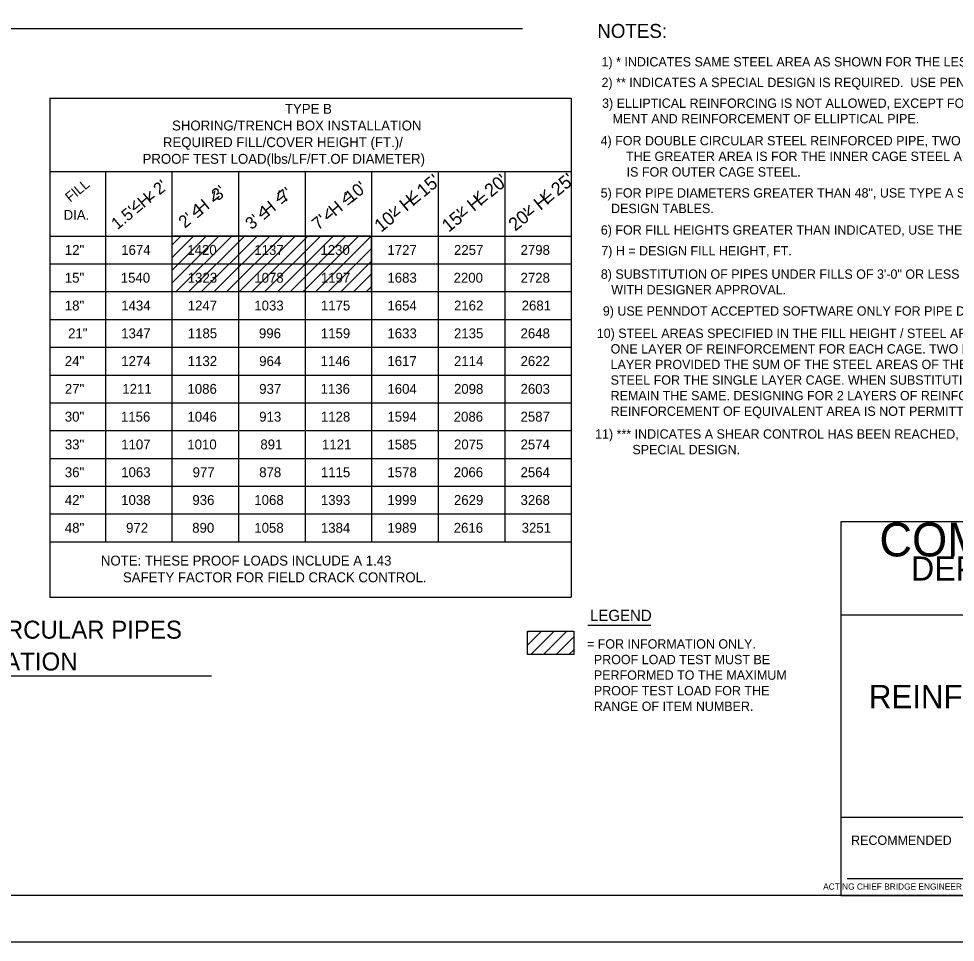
# Model space of a CAD drawing. Extents: x -22562 to -18409, y 3991 to 7171.
# Drawn here: x -20023 to -19722.1, y 3991.4 to 4287.9 of the extents above; entities that cross this region are included whole.
import ezdxf

# ---------------------------------------------------------------- set-up
doc = ezdxf.new("R2010")
doc.units = 0
for name, color, linetype in [('1', 7, 'Continuous'), ('2', 7, 'Continuous'), ('3', 7, 'Continuous'), ('4', 7, 'Continuous'), ('PLT-BNDY', 7, 'Continuous')]:
    doc.layers.add(name, color=color, linetype=linetype)

msp = doc.modelspace()

# ---------------------------------------------------------------- linework, layer by layer
at = {"layer": '1'}
for p, q in [((-20012.97, 4238.78), (-20012.97, 4238.78)), ((-19854.27, 4229.74), (-19853.91, 4233)), ((-19981.02, 4229.57), (-19980.69, 4232.54)), ((-19981.02, 4229.57), (-19979.37, 4230.92)), ((-19960.54, 4229.27), (-19959.91, 4232.58)), ((-19960.54, 4229.27), (-19958.55, 4230.91)), ((-19939.82, 4229.44), (-19939.2, 4232.71)), ((-19918.56, 4229.01), (-19918.03, 4232.23)), ((-19897.1, 4229.47), (-19896.73, 4232.73)), ((-19875.68, 4229.29), (-19875.32, 4232.56)), ((-19986.06, 4226.54), (-19985.73, 4229.51)), ((-19966.74, 4224.97), (-19966.12, 4228.29)), ((-19945.35, 4224.43), (-19944.73, 4227.71)), ((-19924.15, 4223.72), (-19923.62, 4226.94)), ((-19902.28, 4224.43), (-19901.92, 4227.7)), ((-19880.82, 4224.36), (-19880.46, 4227.62)), ((-19859.31, 4224.71), (-19858.95, 4227.97)), ((-19924.05, 4223.75), (-19922.16, 4225.3)), ((-19902.21, 4224.35), (-19900.41, 4225.83)), ((-19880.61, 4224.41), (-19878.81, 4225.89)), ((-19859.15, 4224.76), (-19857.35, 4226.24)), ((-20012.97, 4218.09), (-20012.97, 4218.09)), ((-19973.75, 4218.09), (-19973.75, 4218.09)), ((-19973.75, 4215.2), (-19970.86, 4218.09)), ((-19973.75, 4211.12), (-19966.79, 4218.09)), ((-19973.75, 4207.05), (-19962.71, 4218.09)), ((-19973.75, 4202.97), (-19958.63, 4218.09)), ((-19972.39, 4200.25), (-19954.55, 4218.09)), ((-19968.32, 4200.25), (-19950.47, 4218.09)), ((-19964.24, 4200.25), (-19946.4, 4218.09)), ((-19960.16, 4200.25), (-19942.32, 4218.09)), ((-19956.08, 4200.25), (-19938.24, 4218.09)), ((-19952, 4200.25), (-19934.16, 4218.09)), ((-19947.93, 4200.25), (-19930.09, 4218.09)), ((-19943.85, 4200.25), (-19926.01, 4218.09)), ((-19939.77, 4200.25), (-19921.93, 4218.09)), ((-19935.69, 4200.25), (-19917.85, 4218.09)), ((-19931.62, 4200.25), (-19913.78, 4218.09)), ((-19927.54, 4200.25), (-19909.7, 4218.09)), ((-19909.6, 4218.09), (-19909.6, 4218.09)), ((-20004.05, 4213.63), (-20004.05, 4213.63)), ((-19984.44, 4213.63), (-19984.44, 4213.63)), ((-19963.06, 4213.63), (-19963.06, 4213.63)), ((-19923.46, 4200.25), (-19909.6, 4214.1)), ((-19920.29, 4213.63), (-19920.29, 4213.63)), ((-19898.91, 4213.63), (-19898.91, 4213.63)), ((-19877.53, 4213.63), (-19877.53, 4213.63)), ((-19856.15, 4213.63), (-19856.15, 4213.63)), ((-20012.97, 4209.17), (-20012.97, 4209.17)), ((-19919.38, 4200.25), (-19909.6, 4210.02)), ((-19915.3, 4200.25), (-19909.6, 4205.95)), ((-20004.05, 4204.71), (-20004.05, 4204.71)), ((-19984.44, 4204.71), (-19984.44, 4204.71)), ((-19963.06, 4204.71), (-19963.06, 4204.71)), ((-19920.29, 4204.71), (-19920.29, 4204.71)), ((-19898.91, 4204.71), (-19898.91, 4204.71)), ((-19877.53, 4204.71), (-19877.53, 4204.71)), ((-19856.15, 4204.71), (-19856.15, 4204.71)), ((-20012.97, 4200.25), (-20012.97, 4200.25)), ((-19973.75, 4200.25), (-19973.75, 4200.25)), ((-19911.23, 4200.25), (-19909.6, 4201.87)), ((-19909.6, 4200.25), (-19909.6, 4200.25)), ((-20004.05, 4195.79), (-20004.05, 4195.79)), ((-19984.44, 4195.79), (-19984.44, 4195.79)), ((-19963.06, 4195.79), (-19963.06, 4195.79)), ((-19920.29, 4195.79), (-19920.29, 4195.79)), ((-19898.91, 4195.79), (-19898.91, 4195.79)), ((-19877.53, 4195.79), (-19877.53, 4195.79)), ((-19856.15, 4195.79), (-19856.15, 4195.79)), ((-20012.97, 4191.32), (-20012.97, 4191.32)), ((-20004.05, 4186.87), (-20004.05, 4186.87)), ((-19984.44, 4186.87), (-19984.44, 4186.87)), ((-19963.06, 4186.87), (-19963.06, 4186.87)), ((-19920.29, 4186.87), (-19920.29, 4186.87)), ((-19898.91, 4186.87), (-19898.91, 4186.87)), ((-19877.53, 4186.87), (-19877.53, 4186.87)), ((-19856.15, 4186.87), (-19856.15, 4186.87)), ((-20012.97, 4182.4), (-20012.97, 4182.4)), ((-20004.05, 4177.94), (-20004.05, 4177.94)), ((-19984.44, 4177.94), (-19984.44, 4177.94)), ((-19963.06, 4177.94), (-19963.06, 4177.94)), ((-19920.29, 4177.94), (-19920.29, 4177.94)), ((-19898.91, 4177.94), (-19898.91, 4177.94)), ((-19877.53, 4177.94), (-19877.53, 4177.94)), ((-19856.15, 4177.94), (-19856.15, 4177.94)), ((-20012.97, 4173.48), (-20012.97, 4173.48)), ((-20004.05, 4169.02), (-20004.05, 4169.02)), ((-19984.44, 4169.02), (-19984.44, 4169.02)), ((-19963.06, 4169.02), (-19963.06, 4169.02)), ((-19920.29, 4169.02), (-19920.29, 4169.02)), ((-19898.91, 4169.02), (-19898.91, 4169.02)), ((-19877.53, 4169.02), (-19877.53, 4169.02)), ((-19856.15, 4169.02), (-19856.15, 4169.02)), ((-20012.97, 4164.56), (-20012.97, 4164.56)), ((-20004.05, 4160.1), (-20004.05, 4160.1)), ((-19984.44, 4160.1), (-19984.44, 4160.1)), ((-19963.06, 4160.1), (-19963.06, 4160.1)), ((-19920.29, 4160.1), (-19920.29, 4160.1)), ((-19898.91, 4160.1), (-19898.91, 4160.1)), ((-19877.53, 4160.1), (-19877.53, 4160.1)), ((-19856.15, 4160.1), (-19856.15, 4160.1)), ((-20012.97, 4155.64), (-20012.97, 4155.64)), ((-20004.05, 4151.18), (-20004.05, 4151.18)), ((-19984.44, 4151.18), (-19984.44, 4151.18)), ((-19963.06, 4151.18), (-19963.06, 4151.18)), ((-19920.29, 4151.18), (-19920.29, 4151.18)), ((-19898.91, 4151.18), (-19898.91, 4151.18)), ((-19877.53, 4151.18), (-19877.53, 4151.18)), ((-19856.15, 4151.18), (-19856.15, 4151.18)), ((-20012.97, 4146.72), (-20012.97, 4146.72)), ((-20004.05, 4142.26), (-20004.05, 4142.26)), ((-19984.44, 4142.26), (-19984.44, 4142.26)), ((-19963.06, 4142.26), (-19963.06, 4142.26)), ((-19920.29, 4142.26), (-19920.29, 4142.26)), ((-19898.91, 4142.26), (-19898.91, 4142.26)), ((-19877.53, 4142.26), (-19877.53, 4142.26)), ((-19856.15, 4142.26), (-19856.15, 4142.26)), ((-20012.97, 4137.8), (-20012.97, 4137.8)), ((-20004.05, 4133.34), (-20004.05, 4133.34)), ((-19984.44, 4133.34), (-19984.44, 4133.34)), ((-19963.06, 4133.34), (-19963.06, 4133.34)), ((-19920.29, 4133.34), (-19920.29, 4133.34)), ((-19898.91, 4133.34), (-19898.91, 4133.34)), ((-19877.53, 4133.34), (-19877.53, 4133.34)), ((-19856.15, 4133.34), (-19856.15, 4133.34)), ((-20012.97, 4128.88), (-20012.97, 4128.88)), ((-20004.05, 4124.42), (-20004.05, 4124.42)), ((-19984.44, 4124.42), (-19984.44, 4124.42)), ((-19963.06, 4124.42), (-19963.06, 4124.42)), ((-19920.29, 4124.42), (-19920.29, 4124.42)), ((-19898.91, 4124.42), (-19898.91, 4124.42)), ((-19877.53, 4124.42), (-19877.53, 4124.42)), ((-19856.15, 4124.42), (-19856.15, 4124.42)), ((-19859.55, 4090.82), (-19859.16, 4091.21)), ((-19859.55, 4086.74), (-19855.08, 4091.21)), ((-19858.44, 4083.77), (-19851.01, 4091.21)), ((-19854.37, 4083.77), (-19846.93, 4091.21)), ((-19850.29, 4083.77), (-19844.68, 4089.37)), ((-19846.21, 4083.77), (-19844.68, 4085.3))]:
    msp.add_line(p, q, dxfattribs=at)
for points in [[(-19973.75, 4218.09), (-19973.75, 4200.25), (-19909.6, 4200.25), (-19909.6, 4218.09), (-19973.75, 4218.09)], [(-19859.55, 4091.21), (-19844.68, 4091.21), (-19844.68, 4083.77), (-19859.55, 4083.77), (-19859.55, 4091.21)]]:
    msp.add_lwpolyline(points, dxfattribs=at)
at = {"layer": '2'}
for p, q in [((-20088.88, 4284.71), (-19861.09, 4284.71)), ((-20012.97, 4262.32), (-19845.46, 4262.32)), ((-20012.97, 4262.32), (-20012.97, 4102.12)), ((-19845.46, 4262.32), (-19845.46, 4102.12)), ((-20012.97, 4238.78), (-19845.46, 4238.78)), ((-19995.13, 4238.78), (-19995.13, 4119.96)), ((-19973.75, 4238.78), (-19973.75, 4119.96)), ((-19952.36, 4238.78), (-19952.36, 4119.96)), ((-19930.98, 4238.78), (-19930.98, 4119.96)), ((-19909.6, 4238.78), (-19909.6, 4119.96)), ((-19888.22, 4238.78), (-19888.22, 4119.96)), ((-19866.84, 4238.78), (-19866.84, 4119.96)), ((-20012.97, 4218.09), (-19845.46, 4218.09)), ((-20012.97, 4209.17), (-19845.46, 4209.17)), ((-20012.97, 4200.25), (-19845.46, 4200.25)), ((-20012.97, 4191.32), (-19845.46, 4191.32)), ((-20012.97, 4182.4), (-19845.46, 4182.4)), ((-20012.97, 4173.48), (-19845.46, 4173.48)), ((-20012.97, 4164.56), (-19845.46, 4164.56)), ((-20012.97, 4155.64), (-19845.46, 4155.64)), ((-20012.97, 4146.72), (-19845.46, 4146.72)), ((-20012.97, 4137.8), (-19845.46, 4137.8)), ((-20012.97, 4128.88), (-19845.46, 4128.88)), ((-19558.85, 4126.37), (-19758.85, 4126.37)), ((-19758.85, 4126.37), (-19758.85, 4006.37)), ((-20012.97, 4119.96), (-19845.46, 4119.96)), ((-20012.97, 4102.12), (-19845.46, 4102.12)), ((-19558.85, 4096.37), (-19758.85, 4096.37)), ((-19840.17, 4093.2), (-19819.91, 4093.2)), ((-20181.42, 4076.88), (-19960.99, 4076.88)), ((-19558.85, 4031.37), (-19758.85, 4031.37)), ((-19756.85, 4011.87), (-19689.62, 4011.87)), ((-19558.85, 4006.37), (-20344.85, 4006.37)), ((-19758.85, 4006.37), (-19558.85, 4006.37))]:
    msp.add_line(p, q, dxfattribs=at)
at = {"layer": 'PLT-BNDY'}
msp.add_lwpolyline([(-20384.85, 4585.37), (-19543.85, 4585.37), (-19543.85, 3991.37), (-20384.85, 3991.37)], close=True, dxfattribs=at)

# ---------------------------------------------------------------- texts
at = {"layer": '1'}
for s, height, p in [('TYPE B', 3.172, (-19937.45, 4257.35)), ('SHORING/TRENCH BOX INSTALLATION', 3.1717, (-19973.7, 4251.99)), ('REQUIRED FILL/COVER HEIGHT (FT.)/', 3.1717, (-19976.64, 4246.64)), ('PROOF TEST LOAD(lbs/LF/FT.OF DIAMETER)', 3.1717, (-19983.17, 4241.29)), ('5) FOR PIPE DIAMETERS GREATER THAN 48", USE TYPE A SHORING/TRENCH BOX', 3, (-19836.03, 4230.45)), ('   DESIGN TABLES.', 3, (-19836.03, 4225.45)), ('DIA.', 3.172, (-20008.54, 4223.3)), ('6) FOR FILL HEIGHTS GREATER THAN INDICATED, USE THE PENNDOT ACCEPTED SOFTWARE.', 3, (-19835.97, 4218.55)), ('12"', 3.172, (-20008.15, 4212.04)), ('1674', 3.172, (-19990.04, 4212.04)), ('1420', 3.172, (-19968.8, 4212.04)), ('1230', 3.172, (-19926.04, 4212.04)), ('1727', 3.172, (-19904.52, 4212.04)), ('2257', 3.172, (-19883.14, 4212.04)), ('2798', 3.172, (-19861.76, 4212.04)), ('15"', 3.172, (-20008.15, 4203.12)), ('1540', 3.172, (-19990.18, 4203.12)), ('1323', 3.172, (-19968.66, 4203.12)), ('1197', 3.172, (-19925.9, 4203.12)), ('1683', 3.172, (-19904.52, 4203.12)), ('2200', 3.172, (-19883.27, 4203.12)), ('2728', 3.172, (-19861.76, 4203.12)), ('18"', 3.172, (-20008.15, 4194.2)), ('1434', 3.172, (-19990.04, 4194.2)), ('1247', 3.172, (-19968.66, 4194.2)), ('1175', 3.172, (-19925.9, 4194.2)), ('1654', 3.172, (-19904.52, 4194.2)), ('2162', 3.172, (-19883.14, 4194.2)), ('2681', 3.172, (-19861.4, 4194.2)), ('9) USE PENNDOT ACCEPTED SOFTWARE ONLY FOR PIPE DESIGNS NOT PROVIDED BY BD-636M.', 3, (-19835.33, 4192.54)), ('21"', 3.172, (-20007.1, 4185.28)), ('1347', 3.172, (-19990.04, 4185.28)), ('1185', 3.172, (-19968.66, 4185.28)), ('1159', 3.172, (-19925.91, 4185.28)), ('1633', 3.172, (-19904.52, 4185.28)), ('2135', 3.172, (-19883.14, 4185.28)), ('2648', 3.172, (-19861.76, 4185.28)), ('10) STEEL AREAS SPECIFIED IN THE FILL HEIGHT / STEEL AREA TABLES ARE TO BE ACHIEVED USING', 3, (-19837.28, 4185.38)), ('    ONE LAYER OF REINFORCEMENT FOR EACH CAGE. TWO LAYERS MAY BE SUBSTITUTED FOR ONE', 3, (-19837.28, 4180.38)), ('24"', 3.172, (-20008.15, 4176.36)), ('1274', 3.172, (-19990.04, 4176.36)), ('1132', 3.172, (-19968.66, 4176.36)), ('1146', 3.172, (-19925.99, 4176.36)), ('1617', 3.172, (-19904.52, 4176.36)), ('2114', 3.172, (-19883.14, 4176.36)), ('2622', 3.172, (-19861.76, 4176.36)), ('    LAYER PROVIDED THE SUM OF THE STEEL AREAS OF THE 2 LAYERS IS EQUAL TO THE AREA OF', 3, (-19837.28, 4175.37)), ('    STEEL FOR THE SINGLE LAYER CAGE. WHEN SUBSTITUTING, SPACING OF REINFORCEMENT IS TO', 3, (-19837.28, 4170.37)), ('27"', 3.172, (-20008.15, 4167.44)), ('1211', 3.172, (-19989.68, 4167.44)), ('1086', 3.172, (-19968.75, 4167.44)), ('1136', 3.172, (-19925.99, 4167.44)), ('1604', 3.172, (-19904.52, 4167.44)), ('2098', 3.172, (-19883.14, 4167.44)), ('2603', 3.172, (-19861.76, 4167.44)), ('    REMAIN THE SAME. DESIGNING FOR 2 LAYERS OF REINFORCEMENT AND PROVIDING ONE LAYER OF', 3, (-19837.28, 4165.36)), ('30"', 3.172, (-20008.15, 4158.52)), ('1156', 3.172, (-19990.13, 4158.52)), ('1046', 3.172, (-19968.75, 4158.52)), ('1128', 3.172, (-19925.9, 4158.52)), ('1594', 3.172, (-19904.52, 4158.52)), ('2086', 3.172, (-19883.23, 4158.52)), ('2587', 3.172, (-19861.76, 4158.52)), ('    REINFORCEMENT OF EQUIVALENT AREA IS NOT PERMITTED.', 3, (-19837.28, 4160.36)), ('11) *** INDICATES A SHEAR CONTROL HAS BEEN REACHED, USE PENNDOT ACCEPTED SOFTWARE FOR', 3, (-19837.82, 4153.05)), ('33"', 3.172, (-20008.15, 4149.6)), ('1107', 3.172, (-19990.04, 4149.6)), ('1010', 3.172, (-19968.8, 4149.6)), ('1121', 3.172, (-19925.54, 4149.6)), ('1585', 3.172, (-19904.52, 4149.6)), ('2075', 3.172, (-19883.14, 4149.6)), ('2574', 3.172, (-19861.76, 4149.6)), ('SPECIAL DESIGN.', 3, (-19825.82, 4148.04)), ('36"', 3.172, (-20008.15, 4140.68)), ('1063', 3.172, (-19990.04, 4140.68)), ('977', 3.172, (-19967.09, 4140.68)), ('1115', 3.172, (-19925.9, 4140.68)), ('1578', 3.172, (-19904.52, 4140.68)), ('2066', 3.172, (-19883.22, 4140.68)), ('2564', 3.172, (-19861.76, 4140.68)), ('42"', 3.172, (-20008.15, 4131.76)), ('1038', 3.172, (-19990.05, 4131.76)), ('936', 3.172, (-19967.17, 4131.76)), ('1393', 3.172, (-19925.9, 4131.76)), ('1999', 3.172, (-19904.53, 4131.76)), ('2629', 3.172, (-19883.15, 4131.76)), ('3268', 3.172, (-19861.76, 4131.76)), ('48"', 3.172, (-20008.15, 4122.84)), ('972', 3.172, (-19988.47, 4122.84)), ('890', 3.172, (-19967.23, 4122.84)), ('1384', 3.172, (-19925.9, 4122.84)), ('1989', 3.172, (-19904.53, 4122.84)), ('2616', 3.172, (-19883.23, 4122.84)), ('3251', 3.172, (-19861.4, 4122.84)), ('NOTE: THESE PROOF LOADS INCLUDE A 1.43', 3.1718, (-19996.56, 4112.31)), ('      SAFETY FACTOR FOR FIELD CRACK CONTROL.', 3.1718, (-19996.56, 4106.95)), ('= FOR INFORMATION ONLY.', 3, (-19840.44, 4085.65)), ('  PROOF LOAD TEST MUST BE', 3, (-19840.44, 4080.64)), ('  PERFORMED TO THE MAXIMUM', 3, (-19840.44, 4075.64)), ('  PROOF TEST LOAD FOR THE', 3, (-19840.44, 4070.63)), ('  RANGE OF ITEM NUMBER.', 3, (-19840.44, 4065.63))]:
    msp.add_text(s, height=height, dxfattribs=at).set_placement(p)
for s, height, p in [('FILL', 3.172, (-20006.43, 4228.81)), ('=', 3.93, (-19938.11, 4227.39)), ('=', 3.97, (-19916.75, 4226.98)), ('=', 4.22, (-19895.28, 4227.19)), ('=', 4.22, (-19873.78, 4227.21)), ('=', 4.22, (-19852.41, 4227.56)), ('=', 3.84, (-19984.44, 4224.52)), ('=', 3.97, (-19965.07, 4222.88)), ('=', 3.93, (-19943.69, 4222.36))]:
    msp.add_text(s, height=height, rotation=39.5, dxfattribs=at).set_placement(p)
at = {"layer": '2'}
for s, height, p in [('NOTES:', 4.5, (-19837.1, 4281.69)), ('COMMONWEALTH OF PENNSYLVANIA', 10.8525, (-19746.47, 4115.24)), ('DEPARTMENT OF TRANSPORTATION', 7.7332, (-19736.35, 4107.49)), ('DESIGN TABLES AND PROOF TEST LOAD TABLE FOR CIRCULAR PIPES', 5.7669, (-20236.21, 4088.84)), ('-TYPE B SHORING/TRENCH BOX INSTALLATION', 5.7669, (-20181.88, 4078.62)), ('REINFORCED CONCRETE PIPES', 7.5, (-19749.85, 4066.49)), ('       ACTING CHIEF BRIDGE ENGINEER', 2.0002, (-19769.76, 4008.24))]:
    msp.add_text(s, height=height, dxfattribs=at).set_placement(p)
msp.add_text('RECOMMENDED', height=3, rotation=360, dxfattribs=at).set_placement((-19755.58, 4022.62))
at = {"layer": '3'}
for s, height, p in [('1137', 3.172, (-19947.28, 4212.04)), ('1078', 3.172, (-19947.28, 4203.12)), ('8) SUBSTITUTION OF PIPES UNDER FILLS OF 3\'-0" OR LESS IS PERMITTED ONLY', 3, (-19835.97, 4204.37)), ('   WITH DESIGNER APPROVAL.', 3, (-19835.97, 4199.37)), ('1033', 3.172, (-19947.28, 4194.2)), ('996', 3.172, (-19945.79, 4185.28)), ('964', 3.172, (-19945.71, 4176.36)), ('937', 3.172, (-19945.71, 4167.44)), ('913', 3.172, (-19945.71, 4158.52)), ('891', 3.172, (-19945.34, 4149.6)), ('878', 3.172, (-19945.71, 4140.68)), ('1068', 3.172, (-19947.28, 4131.76)), ('1058', 3.172, (-19947.28, 4122.84))]:
    msp.add_text(s, height=height, dxfattribs=at).set_placement(p)
at = {"layer": '4'}
for s, height, p in [('1) * INDICATES SAME STEEL AREA AS SHOWN FOR THE LESSER CONCRETE STRENGTH.', 3, (-19835.75, 4272.53)), ('2) ** INDICATES A SPECIAL DESIGN IS REQUIRED.  USE PENNDOT ACCEPTED SOFTWARE.', 3, (-19835.75, 4265.9)), ('3) ELLIPTICAL REINFORCING IS NOT ALLOWED, EXCEPT FOR QUADRANT REINFORCE-', 3, (-19835.57, 4259.25)), ('   MENT AND REINFORCEMENT OF ELLIPTICAL PIPE.', 3, (-19835.57, 4254.25)), ('4) FOR DOUBLE CIRCULAR STEEL REINFORCED PIPE, TWO AREAS ARE SHOWN.', 3, (-19836.05, 4247.2)), ('THE GREATER AREA IS FOR THE INNER CAGE STEEL AND LESSER AREA', 3, (-19827.86, 4242.2)), ('IS FOR OUTER CAGE STEEL.', 3, (-19827.68, 4237.19)), ('7) H = DESIGN FILL HEIGHT, FT.', 3, (-19835.83, 4211.85)), ('LEGEND', 3.606, (-19839.46, 4094.5))]:
    msp.add_text(s, height=height, dxfattribs=at).set_placement(p)
for s, height, p in [("1.5'  H  2'", 3.8379, (-19991.28, 4219.93)), ("10'  H  15'", 4.2216, (-19906.55, 4219.1)), ("15'  H  20'", 4.2216, (-19884.86, 4219.11)), ("20'  H  25'", 4.2216, (-19863.45, 4219.47)), ("2'  H  3'", 3.973, (-19969.59, 4220.42)), ("3'  H  7'", 3.934, (-19948.17, 4219.93)), ("7'  H  10'", 3.973, (-19926.75, 4219.81))]:
    msp.add_text(s, height=height, rotation=39.5, dxfattribs=at).set_placement(p)

doc.saveas('drawing.dxf')
